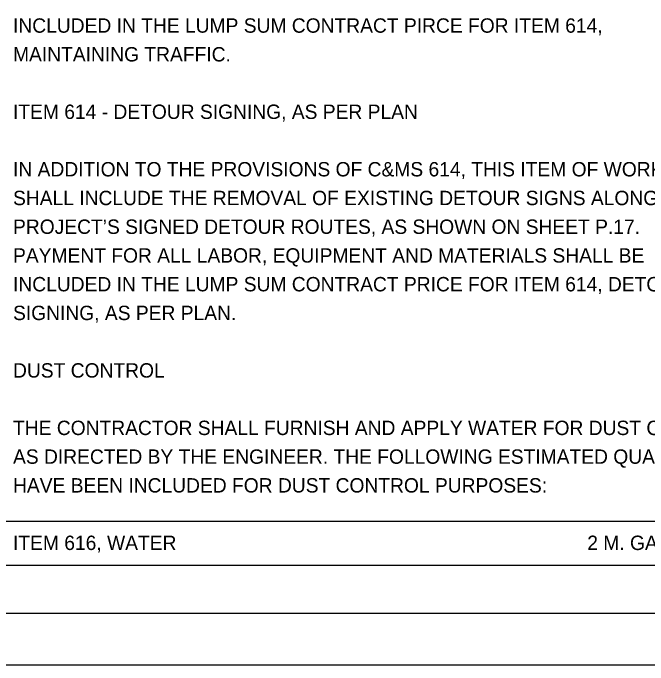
# Model space of a CAD drawing. Extents: x 0 to 34, y -9.1 to 22.
# Drawn here: x 24.66 to 30.84, y 0 to 6.35 of the extents above; entities that cross this region are included whole.
import ezdxf

# ---------------------------------------------------------------- set-up
doc = ezdxf.new("R2010")
doc.units = 0
for name, color, linetype in [('SC_Scratch1', 7, 'Continuous'), ('SH_Border', 7, 'Continuous'), ('SH_Cut_Line', 7, 'Continuous'), ('SH_Text', 7, 'Continuous')]:
    doc.layers.add(name, color=color, linetype=linetype)

msp = doc.modelspace()

# ---------------------------------------------------------------- linework, layer by layer
at = {"layer": 'SC_Scratch1'}
msp.add_lwpolyline([(24.5038, 1.4025), (31.3027, 1.4025), (31.3027, 0.9697), (24.5038, 0.9697)], close=True, dxfattribs=at)
at = {"layer": 'SH_Border'}
msp.add_lwpolyline([(1.5, 21.5), (33.5, 21.5), (33.5, 0.5), (1.5, 0.5)], close=True, dxfattribs=at)
at = {"layer": 'SH_Cut_Line'}
msp.add_lwpolyline([(0, 0), (34, 0), (34, 22), (0, 22)], close=True, dxfattribs=at)

# ---------------------------------------------------------------- texts
at = {"layer": 'SH_Text'}
for s, p in [('INCLUDED IN THE LUMP SUM CONTRACT PIRCE FOR ITEM 614, ', (24.66, 6.16)), ('MAINTAINING TRAFFIC.', (24.66, 5.88)), ('ITEM 614 - DETOUR SIGNING, AS PER PLAN', (24.66, 5.32)), ('IN ADDITION TO THE PROVISIONS OF C&MS 614, THIS ITEM OF WORK ', (24.66, 4.76)), ('SHALL INCLUDE THE REMOVAL OF EXISTING DETOUR SIGNS ALONG THIS ', (24.66, 4.48)), ('PROJECT’S SIGNED DETOUR ROUTES, AS SHOWN ON SHEET P.17. ', (24.66, 4.2)), ('PAYMENT FOR ALL LABOR, EQUIPMENT AND MATERIALS SHALL BE ', (24.66, 3.92)), ('INCLUDED IN THE LUMP SUM CONTRACT PRICE FOR ITEM 614, DETOUR ', (24.66, 3.64)), ('SIGNING, AS PER PLAN.', (24.66, 3.36)), ('DUST CONTROL', (24.66, 2.8)), ('THE CONTRACTOR SHALL FURNISH AND APPLY WATER FOR DUST CONTROL', (24.66, 2.24)), ('AS DIRECTED BY THE ENGINEER. THE FOLLOWING ESTIMATED QUANTITIES', (24.66, 1.96)), ('HAVE BEEN INCLUDED FOR DUST CONTROL PURPOSES:', (24.66, 1.68)), ('ITEM 616, WATER', (24.66, 1.12)), ('2 M. GAL.', (30.2525, 1.12))]:
    msp.add_text(s, height=0.14, dxfattribs=at).set_placement(p)

doc.saveas('drawing.dxf')
